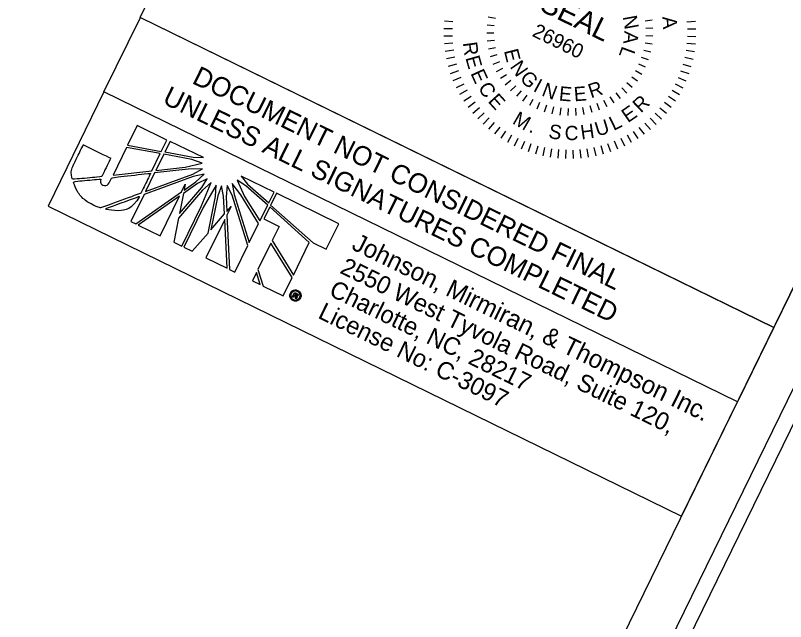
# Model space of a CAD drawing. Extents: x 1517888 to 1526099, y 633375 to 640181.
# Drawn here: x 1522516.7 to 1522953.6, y 634903.4 to 635247.1 of the extents above; entities that cross this region are included whole.
import ezdxf

# ---------------------------------------------------------------- set-up
doc = ezdxf.new("R2010")
doc.units = 0
for name, color, linetype in [('Default', 7, 'Continuous'), ('Sheet Plan CELL', 7, 'Continuous'), ('Sheet Plot Border Inside CELL', 7, 'Continuous'), ('Sheet Plot Border Outside CELL', 7, 'Continuous'), ('Sheet Sticker Exception Certification CELL', 7, 'Continuous')]:
    doc.layers.add(name, color=color, linetype=linetype)

msp = doc.modelspace()

# ---------------------------------------------------------------- linework, layer by layer
at = {"layer": 'Default'}
for p, q in [((1522760.03, 635244.08), (1522764.89, 635243.63)), ((1522784.95, 635246.32), (1522788.94, 635245.55)), ((1522877.89, 635244.39), (1522873.86, 635243.78)), ((1522902.51, 635243.7), (1522897.66, 635243.27)), ((1522759.77, 635239.77), (1522764.64, 635239.61)), ((1522784.31, 635241.81), (1522788.36, 635241.43)), ((1522878.34, 635239.86), (1522874.28, 635239.64)), ((1522902.76, 635239.38), (1522897.89, 635239.25)), ((1522759.75, 635235.45), (1522764.63, 635235.58)), ((1522784.12, 635237.26), (1522788.17, 635237.28)), ((1522878.36, 635235.3), (1522874.29, 635235.48)), ((1522902.74, 635235.06), (1522897.88, 635235.23)), ((1522760, 635231.13), (1522764.86, 635231.57)), ((1522784.35, 635232.72), (1522788.39, 635233.11)), ((1522877.93, 635230.76), (1522873.9, 635231.34)), ((1522902.48, 635230.75), (1522897.62, 635231.2)), ((1522760.51, 635226.84), (1522765.33, 635227.57)), ((1522785.02, 635228.2), (1522789.01, 635229)), ((1522877.07, 635226.29), (1522873.12, 635227.25)), ((1522901.95, 635226.47), (1522897.12, 635227.22)), ((1522761.28, 635222.6), (1522766.04, 635223.6)), ((1522786.13, 635223.79), (1522790.01, 635224.96)), ((1522875.78, 635221.92), (1522871.95, 635223.26)), ((1522901.15, 635222.21), (1522896.39, 635223.26)), ((1522762.3, 635218.39), (1522767, 635219.69)), ((1522787.65, 635219.5), (1522791.41, 635221.04)), ((1522874.08, 635217.69), (1522870.39, 635219.39)), ((1522900.11, 635218.02), (1522895.42, 635219.35)), ((1522763.58, 635214.27), (1522768.19, 635215.84)), ((1522789.59, 635215.37), (1522793.17, 635217.27)), ((1522791.91, 635211.45), (1522795.3, 635213.69)), ((1522871.97, 635213.65), (1522868.47, 635215.7)), ((1522898.81, 635213.9), (1522894.21, 635215.51)), ((1522765.1, 635210.22), (1522769.6, 635212.07)), ((1522794.6, 635207.77), (1522797.76, 635210.33)), ((1522866.65, 635206.27), (1522863.6, 635208.95)), ((1522866.28, 635212.33), (1522869.58, 635209.96)), ((1522897.27, 635209.87), (1522892.77, 635211.75)), ((1522766.86, 635206.27), (1522771.25, 635208.4)), ((1522768.86, 635202.45), (1522773.11, 635204.83)), ((1522797.63, 635204.37), (1522800.53, 635207.22)), ((1522803.57, 635204.41), (1522800.95, 635201.3)), ((1522863.48, 635203), (1522860.7, 635205.96)), ((1522893.46, 635202.11), (1522889.22, 635204.51)), ((1522895.48, 635205.93), (1522891.11, 635208.08)), ((1522771.08, 635198.74), (1522775.18, 635201.37)), ((1522804.61, 635198.53), (1522806.9, 635201.88)), ((1522856.27, 635197.46), (1522854.11, 635200.89)), ((1522860, 635200.06), (1522857.53, 635203.28)), ((1522891.22, 635198.42), (1522887.13, 635201.07)), ((1522773.53, 635195.18), (1522777.46, 635198.06)), ((1522808.48, 635196.13), (1522810.44, 635199.7)), ((1522812.57, 635194.13), (1522814.19, 635197.86)), ((1522816.84, 635192.53), (1522818.08, 635196.4)), ((1522843.8, 635191.97), (1522842.71, 635195.89)), ((1522848.12, 635193.4), (1522846.67, 635197.18)), ((1522852.29, 635195.22), (1522850.48, 635198.86)), ((1522888.76, 635194.87), (1522884.84, 635197.77)), ((1522776.19, 635191.77), (1522779.93, 635194.88)), ((1522779.04, 635188.52), (1522782.6, 635191.86)), ((1522821.24, 635191.35), (1522822.1, 635195.33)), ((1522825.73, 635190.6), (1522826.2, 635194.64)), ((1522830.27, 635190.29), (1522830.36, 635194.35)), ((1522834.83, 635190.41), (1522834.52, 635194.46)), ((1522839.35, 635190.97), (1522838.65, 635194.97)), ((1522883.21, 635188.24), (1522879.66, 635191.6)), ((1522886.09, 635191.48), (1522882.35, 635194.6)), ((1522782.08, 635185.46), (1522785.44, 635189.01)), ((1522880.15, 635185.2), (1522876.82, 635188.76)), ((1522585.76, 635184.67), (1522580.31, 635173.51)), ((1522602.59, 635176.46), (1522585.76, 635184.67)), ((1522785.32, 635182.59), (1522788.44, 635186.33)), ((1522788.71, 635179.91), (1522791.6, 635183.83)), ((1522873.5, 635179.69), (1522870.62, 635183.63)), ((1522876.9, 635182.35), (1522873.79, 635186.1)), ((1522792.26, 635177.46), (1522794.91, 635181.54)), ((1522795.95, 635175.21), (1522798.35, 635179.45)), ((1522866.23, 635175.02), (1522863.85, 635179.27)), ((1522869.93, 635177.24), (1522867.3, 635181.35)), ((1522599.42, 635169.97), (1522602.59, 635176.46)), ((1522604.38, 635175.69), (1522601.44, 635169.67)), ((1522623.31, 635166.46), (1522604.38, 635175.69)), ((1522799.77, 635173.19), (1522801.92, 635177.57)), ((1522803.71, 635171.4), (1522805.59, 635175.9)), ((1522807.74, 635169.86), (1522809.35, 635174.46)), ((1522854.41, 635169.74), (1522852.83, 635174.35)), ((1522858.45, 635171.26), (1522856.6, 635175.77)), ((1522862.4, 635173.02), (1522860.28, 635177.41)), ((1522579.69, 635172.23), (1522572.04, 635156.55)), ((1522598.82, 635168.75), (1522579.69, 635172.23)), ((1522580.31, 635173.51), (1522599.42, 635169.97)), ((1522601.44, 635169.67), (1522617.44, 635166.67)), ((1522811.86, 635168.56), (1522813.18, 635173.25)), ((1522816.05, 635167.52), (1522817.09, 635172.28)), ((1522820.3, 635166.72), (1522821.06, 635171.55)), ((1522824.59, 635166.19), (1522825.04, 635171.05)), ((1522828.9, 635165.93), (1522829.07, 635170.8)), ((1522833.22, 635165.91), (1522833.09, 635170.79)), ((1522837.54, 635166.16), (1522837.11, 635171.02)), ((1522841.83, 635166.67), (1522841.11, 635171.49)), ((1522846.08, 635167.44), (1522845.07, 635172.21)), ((1522850.28, 635168.46), (1522848.98, 635173.16)), ((1522594.07, 635159), (1522598.82, 635168.75)), ((1522600.8, 635168.36), (1522596.36, 635159.26)), ((1522616.8, 635165.37), (1522600.8, 635168.36)), ((1522622.63, 635163.35), (1522616.8, 635165.37)), ((1522617.44, 635166.67), (1522623.31, 635166.46)), ((1522596.36, 635159.26), (1522612.89, 635161.09)), ((1522612.89, 635161.09), (1522622.63, 635163.35)), ((1522572.04, 635156.55), (1522594.07, 635159)), ((1522595.64, 635157.78), (1522590.52, 635147.29)), ((1522590.52, 635147.29), (1522617.27, 635157.1)), ((1522614.74, 635159.95), (1522595.64, 635157.78)), ((1522622.74, 635160.07), (1522614.74, 635159.95)), ((1522617.27, 635157.1), (1522622.74, 635160.07)), ((1522623.7, 635157.09), (1522617.54, 635155.83)), ((1522619.01, 635152.71), (1522623.7, 635157.09)), ((1522617.54, 635155.83), (1522589.65, 635145.51)), ((1522612.36, 635148.01), (1522619.01, 635152.71)), ((1522625.38, 635154.41), (1522619.96, 635151.76)), ((1522622.04, 635138.68), (1522627.79, 635152.31)), ((1522622.37, 635149.45), (1522625.38, 635154.41)), ((1522627.79, 635152.31), (1522622.86, 635148.05)), ((1522642.45, 635153.68), (1522646.69, 635144.46)), ((1522647.32, 635150.48), (1522642.45, 635153.68)), ((1522663.37, 635146.81), (1522644.75, 635156)), ((1522644.75, 635156), (1522648.39, 635151.47)), ((1522622.86, 635148.05), (1522609.24, 635132.18)), ((1522609.82, 635134.78), (1522622.37, 635149.45)), ((1522610.85, 635147.03), (1522613.01, 635151.47)), ((1522619.96, 635151.76), (1522612.06, 635146.2)), ((1522613.01, 635151.47), (1522612.36, 635148.01)), ((1522630.57, 635150.95), (1522623.23, 635138.1)), ((1522630.16, 635144.48), (1522630.57, 635150.95)), ((1522633.63, 635150.39), (1522631.55, 635144.73)), ((1522634.79, 635144.53), (1522633.63, 635150.39)), ((1522636.75, 635150.72), (1522636.17, 635144.33)), ((1522639.54, 635145.1), (1522636.75, 635150.72)), ((1522639.71, 635151.79), (1522640.69, 635145.57)), ((1522644.62, 635145.37), (1522639.71, 635151.79)), ((1522659.79, 635139.48), (1522647.32, 635150.48)), ((1522648.39, 635151.47), (1522660.41, 635140.76)), ((1522589.65, 635145.51), (1522582.2, 635130.24)), ((1522584.98, 635128.89), (1522610.85, 635147.03)), ((1522609.67, 635144.62), (1522586.28, 635128.25)), ((1522598.83, 635122.13), (1522609.67, 635144.62)), ((1522612.06, 635146.2), (1522609.82, 635134.78)), ((1522625.98, 635123.66), (1522630.16, 635144.48)), ((1522631.55, 635144.73), (1522627.62, 635125.61)), ((1522635.3, 635134.52), (1522634.79, 635144.53)), ((1522636.17, 635144.33), (1522636.52, 635135.88)), ((1522648.49, 635116.6), (1522639.54, 635145.1)), ((1522640.69, 635145.57), (1522649.34, 635118.35)), ((1522654.6, 635129.12), (1522644.62, 635145.37)), ((1522646.69, 635144.46), (1522655.33, 635130.62)), ((1522660.41, 635140.76), (1522663.37, 635146.81)), ((1522664.71, 635146.26), (1522661.54, 635139.76)), ((1522700.09, 635129), (1522664.71, 635146.26)), ((1522655.33, 635130.62), (1522659.79, 635139.48)), ((1522661.54, 635139.76), (1522661.45, 635139.56)), ((1522661.45, 635139.56), (1522685.49, 635118.17)), ((1522611.09, 635116.25), (1522622.04, 635138.68)), ((1522623.23, 635138.1), (1522612.28, 635115.67)), ((1522627.62, 635125.61), (1522635.3, 635134.52)), ((1522636.52, 635135.88), (1522639, 635138.79)), ((1522639, 635138.79), (1522636.61, 635133.88)), ((1522660.91, 635138.45), (1522657.6, 635131.68)), ((1522660.96, 635138.56), (1522660.91, 635138.45)), ((1522683.4, 635118.4), (1522660.96, 635138.56)), ((1522582.2, 635130.24), (1522584.98, 635128.89)), ((1522609.24, 635132.18), (1522606.48, 635118.5)), ((1522635.43, 635131.46), (1522624.75, 635109.58)), ((1522636.8, 635103.7), (1522635.43, 635131.46)), ((1522636.61, 635133.88), (1522638.15, 635102.94)), ((1522657.6, 635131.68), (1522666.24, 635127.47)), ((1522586.28, 635128.25), (1522598.83, 635122.13)), ((1522649.34, 635118.35), (1522654.6, 635129.12)), ((1522666.24, 635127.47), (1522662.29, 635119.39)), ((1522693.02, 635114.5), (1522700.09, 635129)), ((1522616.95, 635113.39), (1522625.98, 635123.66)), ((1522606.48, 635118.5), (1522611.09, 635116.25)), ((1522661.62, 635118), (1522654.27, 635102.95)), ((1522673.7, 635098.52), (1522661.62, 635118)), ((1522662.29, 635119.39), (1522674.34, 635099.83)), ((1522674.34, 635099.83), (1522683.4, 635118.4)), ((1522685.49, 635118.17), (1522693.02, 635114.5)), ((1522612.28, 635115.67), (1522616.95, 635113.39)), ((1522641.12, 635101.49), (1522648.49, 635116.6)), ((1522624.75, 635109.58), (1522636.8, 635103.7)), ((1522638.15, 635102.94), (1522641.12, 635101.49)), ((1522653.48, 635101.31), (1522651.17, 635096.59)), ((1522655.53, 635094.46), (1522653.48, 635101.31)), ((1522654.27, 635102.95), (1522657.2, 635093.65)), ((1522651.17, 635096.59), (1522655.53, 635094.46)), ((1522668.61, 635088.08), (1522673.7, 635098.52)), ((1522657.2, 635093.65), (1522668.61, 635088.08)), ((1522676.86, 635091.09), (1522676.6, 635090.55)), ((1522676.6, 635090.55), (1522676.86, 635091.09)), ((1522673.82, 635087.51), (1522675.07, 635090.08)), ((1522674.4, 635087.22), (1522673.82, 635087.51)), ((1522674.89, 635088.23), (1522674.4, 635087.22)), ((1522675.36, 635088), (1522674.89, 635088.23)), ((1522675.07, 635090.08), (1522676.12, 635089.57)), ((1522675.42, 635089.3), (1522675.12, 635088.7)), ((1522675.12, 635088.7), (1522675.59, 635088.47)), ((1522675.59, 635088.47), (1522675.36, 635088)), ((1522675.36, 635088), (1522675.59, 635088.47)), ((1522675.38, 635087.99), (1522675.36, 635088)), ((1522675.88, 635089.08), (1522675.42, 635089.3)), ((1522675.59, 635088.47), (1522675.61, 635088.46)), ((1522676.12, 635089.57), (1522675.88, 635089.08)), ((1522675.88, 635089.08), (1522676.12, 635089.57)), ((1522675.95, 635089.04), (1522675.88, 635089.08)), ((1522676.12, 635089.57), (1522676.29, 635089.49)), ((1522674.38, 635085.99), (1522674.1, 635085.43)), ((1522674.1, 635085.43), (1522674.38, 635085.99)), ((1522674.13, 635085.42), (1522674.1, 635085.43)), ((1522674.38, 635085.99), (1522674.4, 635085.98))]:
    msp.add_line(p, q, dxfattribs=at)
msp.add_lwpolyline([(1522535.19, 635138.9), (1522894.58, 634963.13), (1522926.3, 635027.99), (1522566.91, 635203.76)], close=True, dxfattribs=at)
for points in [[(1522580.31, 635173.51), (1522599.42, 635169.97), (1522602.59, 635176.46), (1522585.76, 635184.67), (1522580.31, 635173.51)], [(1522617.44, 635166.67), (1522623.31, 635166.46), (1522604.38, 635175.69), (1522601.44, 635169.67), (1522617.44, 635166.67)], [(1522572.04, 635156.55), (1522594.07, 635159), (1522598.82, 635168.75), (1522579.69, 635172.23), (1522572.04, 635156.55)], [(1522600.8, 635168.36), (1522596.36, 635159.26), (1522612.89, 635161.09), (1522622.63, 635163.35), (1522616.8, 635165.37), (1522600.8, 635168.36)], [(1522623.7, 635157.09), (1522617.54, 635155.83), (1522589.65, 635145.51), (1522582.2, 635130.24), (1522584.98, 635128.89), (1522610.85, 635147.03), (1522613.01, 635151.47), (1522612.36, 635148.01), (1522619.01, 635152.71), (1522623.7, 635157.09)], [(1522595.64, 635157.78), (1522590.52, 635147.29), (1522617.27, 635157.1), (1522622.74, 635160.07), (1522614.74, 635159.95), (1522595.64, 635157.78)], [(1522622.86, 635148.05), (1522609.24, 635132.18), (1522606.48, 635118.5), (1522611.09, 635116.25), (1522622.04, 635138.68), (1522627.79, 635152.31), (1522622.86, 635148.05)], [(1522625.38, 635154.41), (1522619.96, 635151.76), (1522612.06, 635146.2), (1522609.82, 635134.78), (1522622.37, 635149.45), (1522625.38, 635154.41)], [(1522642.45, 635153.68), (1522646.69, 635144.46), (1522655.33, 635130.62), (1522659.79, 635139.48), (1522647.32, 635150.48), (1522642.45, 635153.68)], [(1522648.39, 635151.47), (1522660.41, 635140.76), (1522663.37, 635146.81), (1522644.75, 635156), (1522648.39, 635151.47)], [(1522630.57, 635150.95), (1522623.23, 635138.1), (1522612.28, 635115.67), (1522616.95, 635113.39), (1522625.98, 635123.66), (1522630.16, 635144.48), (1522630.57, 635150.95)], [(1522633.63, 635150.39), (1522631.55, 635144.73), (1522627.62, 635125.61), (1522635.3, 635134.52), (1522634.79, 635144.53), (1522633.63, 635150.39)], [(1522636.75, 635150.72), (1522636.17, 635144.33), (1522636.52, 635135.88), (1522639, 635138.79), (1522636.61, 635133.88), (1522638.15, 635102.94), (1522641.12, 635101.49), (1522648.49, 635116.6), (1522639.54, 635145.1), (1522636.75, 635150.72)], [(1522639.71, 635151.79), (1522640.69, 635145.57), (1522649.34, 635118.35), (1522654.6, 635129.12), (1522644.62, 635145.37), (1522639.71, 635151.79)], [(1522586.28, 635128.25), (1522598.83, 635122.13), (1522609.67, 635144.62), (1522586.28, 635128.25)], [(1522700.09, 635129), (1522664.71, 635146.26), (1522661.54, 635139.76), (1522661.45, 635139.56), (1522685.49, 635118.17), (1522693.02, 635114.5), (1522700.09, 635129)], [(1522660.96, 635138.56), (1522660.91, 635138.45), (1522657.6, 635131.68), (1522666.24, 635127.47), (1522662.29, 635119.39), (1522674.34, 635099.83), (1522683.4, 635118.4), (1522660.96, 635138.56)], [(1522624.75, 635109.58), (1522636.8, 635103.7), (1522635.43, 635131.46), (1522624.75, 635109.58)], [(1522661.62, 635118), (1522654.27, 635102.95), (1522657.2, 635093.65), (1522668.61, 635088.08), (1522673.7, 635098.52), (1522661.62, 635118), (1522661.62, 635118)], [(1522651.17, 635096.59), (1522651.17, 635096.59), (1522655.53, 635094.46), (1522653.48, 635101.31), (1522651.17, 635096.59)], [(1522676.29, 635087.05), (1522676.22, 635086.91), (1522676.2, 635086.81), (1522676.15, 635086.72), (1522676.08, 635086.4), (1522675.55, 635086.66)]]:
    msp.add_lwpolyline(points, dxfattribs=at)
for points, degree in [([(1522570.73, 635166.12), (1522570.73, 635166.12), (1522555.15, 635173.72), (1522555.15, 635173.72), (1522555.15, 635173.72), (1522550.4, 635163.98), (1522550.4, 635163.98), (1522550.4, 635163.98), (1522549.89, 635162.95), (1522549.89, 635162.95), (1522548.4, 635159.9), (1522548.23, 635156.99), (1522549.01, 635154.1), (1522549.01, 635154.1), (1522565.61, 635155.63), (1522565.7, 635155.82), (1522565.7, 635155.82), (1522570.73, 635166.12), (1522570.73, 635166.12)], 3), ([(1522566.3, 635150.92), (1522565.3, 635151.41), (1522564.71, 635152.39), (1522565.26, 635154.42), (1522565.26, 635154.42), (1522549.54, 635152.85), (1522549.54, 635152.85), (1522551.35, 635147.12), (1522556.15, 635141.88), (1522561.18, 635139.43), (1522562.48, 635138.8), (1522563.54, 635138.42), (1522565.06, 635138.02), (1522565.06, 635138.02), (1522587.86, 635146.28), (1522587.86, 635146.28), (1522587.86, 635146.28), (1522593.39, 635157.61), (1522593.39, 635157.61), (1522593.39, 635157.61), (1522571.35, 635155.13), (1522571.35, 635155.13), (1522569.27, 635150.88), (1522567.69, 635150.25), (1522566.3, 635150.92)], 3), ([(1522566.3, 635150.92), (1522565.3, 635151.41), (1522564.71, 635152.39), (1522565.26, 635154.42), (1522565.26, 635154.42), (1522549.54, 635152.85), (1522549.54, 635152.85), (1522551.35, 635147.12), (1522556.15, 635141.88), (1522561.18, 635139.43), (1522562.48, 635138.8), (1522563.54, 635138.42), (1522565.06, 635138.02), (1522565.06, 635138.02), (1522587.86, 635146.28), (1522587.86, 635146.28), (1522587.86, 635146.28), (1522593.39, 635157.61), (1522593.39, 635157.61), (1522593.39, 635157.61), (1522571.35, 635155.13), (1522571.35, 635155.13), (1522569.27, 635150.88), (1522567.69, 635150.25), (1522566.3, 635150.92)], 3), ([(1522586.99, 635144.51), (1522586.99, 635144.51), (1522567.29, 635137.38), (1522567.29, 635137.38), (1522574.48, 635135.83), (1522582.94, 635136.96), (1522586.99, 635144.51)], 3), ([(1522674.1, 635085.43), (1522673.33, 635085.8), (1522672.79, 635086.42), (1522672.5, 635087.25), (1522672.2, 635088.06), (1522672.25, 635088.88), (1522672.64, 635089.67), (1522673.03, 635090.47), (1522673.64, 635091.01), (1522674.45, 635091.25), (1522675.28, 635091.51), (1522676.07, 635091.48), (1522676.86, 635091.09)], 3), ([(1522676.6, 635090.55), (1522675.97, 635090.86), (1522675.33, 635090.91), (1522674.68, 635090.7), (1522674.02, 635090.48), (1522673.51, 635090.03), (1522673.2, 635089.4), (1522672.9, 635088.77), (1522672.86, 635088.09), (1522673.08, 635087.43), (1522673.31, 635086.77), (1522673.75, 635086.3), (1522674.38, 635085.99)], 3), ([(1522676.86, 635091.09), (1522677.66, 635090.7), (1522678.2, 635090.09), (1522678.5, 635089.28), (1522678.81, 635088.49), (1522678.76, 635087.67), (1522678.37, 635086.88)], 3), ([(1522678.37, 635086.88), (1522677.98, 635086.08), (1522677.37, 635085.54), (1522676.56, 635085.24), (1522675.74, 635084.98), (1522674.92, 635085.03), (1522674.13, 635085.42)], 3), ([(1522674.4, 635085.98), (1522675.03, 635085.67), (1522675.67, 635085.62), (1522676.33, 635085.85), (1522676.99, 635086.07), (1522677.5, 635086.52), (1522677.81, 635087.15), (1522678.12, 635087.78), (1522678.16, 635088.46), (1522677.93, 635089.12), (1522677.69, 635089.76), (1522677.26, 635090.23), (1522676.6, 635090.55)], 3), ([(1522675.78, 635087.68), (1522675.73, 635087.76), (1522675.62, 635087.87), (1522675.38, 635087.99)], 2), ([(1522675.55, 635086.66), (1522675.54, 635086.84), (1522675.57, 635087), (1522675.66, 635087.19), (1522675.77, 635087.42), (1522675.82, 635087.57), (1522675.78, 635087.68)], 3), ([(1522675.61, 635088.46), (1522675.98, 635088.27), (1522676.23, 635088.3), (1522676.33, 635088.51), (1522676.42, 635088.7), (1522676.3, 635088.87), (1522675.95, 635089.04)], 3), ([(1522676.29, 635089.49), (1522676.94, 635089.17), (1522677.14, 635088.75), (1522676.89, 635088.24), (1522676.78, 635088), (1522676.59, 635087.86), (1522676.31, 635087.82)], 3), ([(1522676.31, 635087.82), (1522676.43, 635087.65), (1522676.42, 635087.39), (1522676.29, 635087.05)], 2)]:
    msp.add_open_spline(points, degree=degree, dxfattribs=at)
at = {"layer": 'Sheet Plan CELL'}
for points in [[(1523067.8, 635317.31), (1520372.85, 636635.35), (1519450.22, 634748.89), (1522145.17, 633430.84)], [(1522686.38, 635448.09), (1523045.79, 635272.3), (1522946.94, 635070.18), (1522587.52, 635245.97)], [(1522686.38, 635448.09), (1523045.79, 635272.3), (1522946.95, 635070.21), (1522587.53, 635245.99)]]:
    msp.add_lwpolyline(points, close=True, dxfattribs=at)
at = {"layer": 'Sheet Plot Border Inside CELL'}
msp.add_lwpolyline([(1519172.24, 634879.28), (1522165.43, 633415.37), (1523092.46, 635310.82), (1520099.27, 636774.73)], close=True, dxfattribs=at)
at = {"layer": 'Sheet Plot Border Outside CELL'}
msp.add_lwpolyline([(1519131.31, 634854.77), (1522155.94, 633375.48), (1523118.12, 635342.8), (1520093.48, 636822.08)], close=True, dxfattribs=at)
at = {"layer": 'Sheet Sticker Exception Certification CELL'}
for p, q in [((1522566.91, 635203.76), (1522587.56, 635245.98)), ((1522587.56, 635245.98), (1522946.95, 635070.21)), ((1522926.3, 635027.99), (1522566.91, 635203.76)), ((1522946.94, 635070.18), (1522926.29, 635027.96))]:
    msp.add_line(p, q, dxfattribs=at)

# ---------------------------------------------------------------- texts
at = {"layer": 'Default'}
for s, height, rotation, p in [('SEAL', 12.189, 333.8847, (1522813.26, 635250.31)), ('N', 8.12, 280.3478, (1522861.1, 635246.39)), ('A', 8.12, 274.4018, (1522883.62, 635246.35)), ('26960', 8.119, 333.8847, (1522809.33, 635235.6)), ('A', 8.12, 265.0516, (1522862.17, 635238.46)), ('R', 8.12, 277.8197, (1522770.45, 635231.59)), ('E', 8.12, 283.9548, (1522793.77, 635227.07)), ('L', 8.12, 249.7554, (1522860.99, 635230.09)), ('E', 8.12, 285.8915, (1522771.88, 635223.08)), ('N', 8.12, 304.8099, (1522796.92, 635217.99)), ('E', 8.12, 294.5343, (1522774.71, 635214.32)), ('G', 8.12, 313.5761, (1522802.38, 635211.08)), ('C', 8.12, 303.2069, (1522778.82, 635206.09)), ('I', 8.12, 331.6709, (1522809.92, 635204.48)), ('N', 8.12, 339.3006, (1522814.75, 635201.82)), ('R', 8.12, 18.4496, (1522843.22, 635200.04)), ('E', 8.12, 354.6926, (1522824.78, 635198.92)), ('E', 8.12, 4.6785, (1522833.78, 635198.36)), ('E', 8.12, 312.1794, (1522784.37, 635198.27)), ('R', 8.12, 43.5571, (1522871.51, 635191.48)), ('E', 8.12, 34.8844, (1522864.14, 635185.95)), ('M', 8.12, 329.9747, (1522798.11, 635186.08)), ('U', 8.12, 17.2091, (1522846.87, 635178.37)), ('L', 8.12, 26.0918, (1522856.03, 635181.6)), ('S', 8.12, 350.5013, (1522818.72, 635177.64)), ('C', 8.12, 359.5039, (1522828.23, 635176.41)), ('H', 8.12, 8.3265, (1522837.82, 635176.7)), ('.', 8.12, 337.717, (1522807.52, 635181.19)), ('Johnson, Mirmiran, & Thompson Inc.', 10.2224, 333.9377, (1522706.79, 635114.76)), ('2550 West Tyvola Road, Suite 120,', 9.9303, 333.9377, (1522700.2, 635101.29)), ('Charlotte, NC, 28217', 9.9303, 333.9377, (1522693.96, 635088.54)), ('License No: C-3097', 9.9303, 333.9377, (1522687.73, 635075.79))]:
    msp.add_text(s, height=height, rotation=rotation, dxfattribs=at).set_placement(p)
at = {"layer": 'Sheet Sticker Exception Certification CELL'}
for s, p in [('DOCUMENT NOT CONSIDERED FINAL', (1522616.32, 635208.88)), ('UNLESS ALL SIGNATURES COMPLETED', (1522599.48, 635197.52))]:
    msp.add_text(s, height=11, rotation=333.9377, dxfattribs=at).set_placement(p)

doc.saveas('drawing.dxf')
